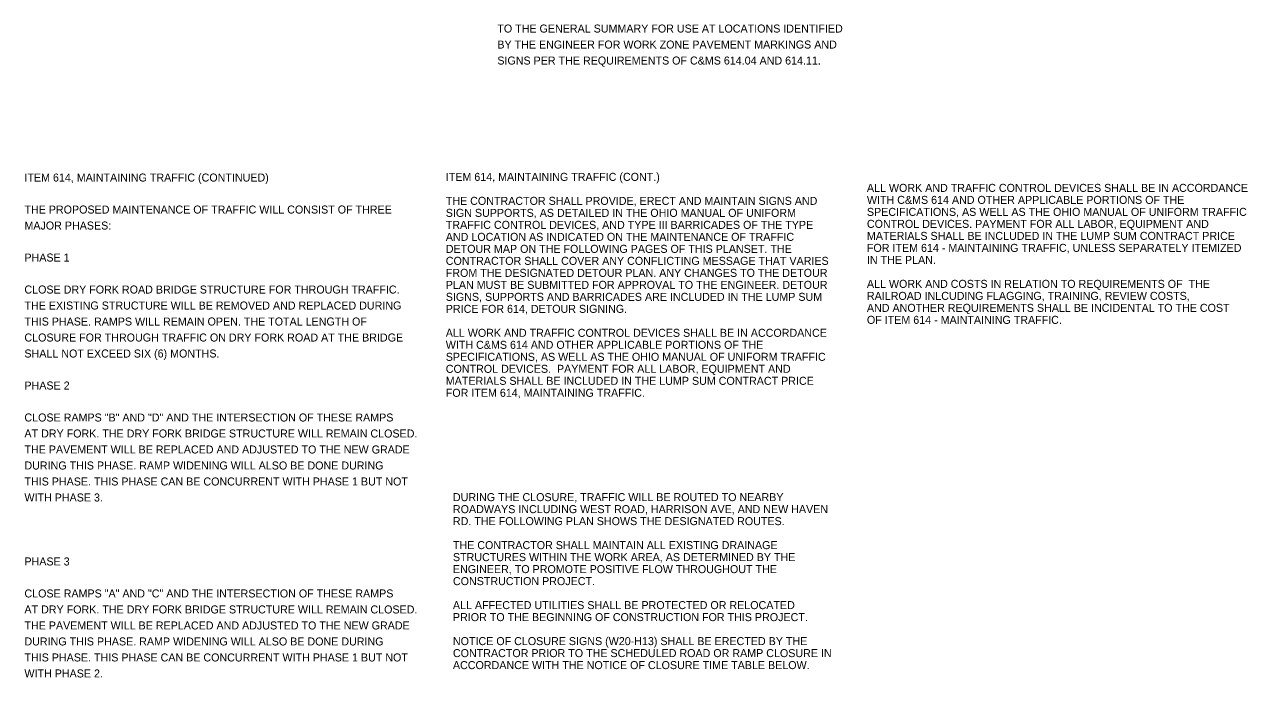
# Model space of a CAD drawing. Extents: x -65.5 to 34, y -24.3 to 23.1.
# Drawn here: x -65.5 to -44.1, y -0.83 to 10.6 of the extents above; entities that cross this region are included whole.
import ezdxf

# ---------------------------------------------------------------- set-up
doc = ezdxf.new("R2010")
doc.units = 0
doc.layers.add('SH_Text', color=7, linetype='Continuous')

msp = doc.modelspace()

# ---------------------------------------------------------------- texts
at = {"layer": 'SH_Text'}
for s, p in [('TO THE GENERAL SUMMARY FOR USE AT LOCATIONS IDENTIFIED', (-57.226, 10.462)), ('BY THE ENGINEER FOR WORK ZONE PAVEMENT MARKINGS AND', (-57.226, 10.182)), ('SIGNS PER THE REQUIREMENTS OF C&MS 614.04 AND 614.11.', (-57.226, 9.902)), ('ITEM 614, MAINTAINING TRAFFIC (CONTINUED)', (-65.5, 7.854)), ('ITEM 614, MAINTAINING TRAFFIC (CONT.)', (-58.128, 7.866)), ('ALL WORK AND TRAFFIC CONTROL DEVICES SHALL BE IN ACCORDANCE ', (-50.76, 7.673)), ('THE CONTRACTOR SHALL PROVIDE, ERECT AND MAINTAIN SIGNS AND ', (-58.128, 7.446)), ('WITH C&MS 614 AND OTHER APPLICABLE PORTIONS OF THE ', (-50.76, 7.463)), ('THE PROPOSED MAINTENANCE OF TRAFFIC WILL CONSIST OF THREE', (-65.5, 7.294)), ('SIGN SUPPORTS, AS DETAILED IN THE OHIO MANUAL OF UNIFORM ', (-58.128, 7.236)), ('SPECIFICATIONS, AS WELL AS THE OHIO MANUAL OF UNIFORM TRAFFIC ', (-50.76, 7.253)), ('MAJOR PHASES:', (-65.5, 7.014)), ('TRAFFIC CONTROL DEVICES, AND TYPE III BARRICADES OF THE TYPE ', (-58.128, 7.026)), ('CONTROL DEVICES. PAYMENT FOR ALL LABOR, EQUIPMENT AND ', (-50.76, 7.043)), ('AND LOCATION AS INDICATED ON THE MAINTENANCE OF TRAFFIC ', (-58.128, 6.816)), ('MATERIALS SHALL BE INCLUDED IN THE LUMP SUM CONTRACT PRICE ', (-50.76, 6.833)), ('DETOUR MAP ON THE FOLLOWING PAGES OF THIS PLANSET. THE ', (-58.128, 6.606)), ('FOR ITEM 614 - MAINTAINING TRAFFIC, UNLESS SEPARATELY ITEMIZED ', (-50.76, 6.623)), ('PHASE 1', (-65.5, 6.454)), ('CONTRACTOR SHALL COVER ANY CONFLICTING MESSAGE THAT VARIES ', (-58.128, 6.396)), ('IN THE PLAN.', (-50.76, 6.413)), ('FROM THE DESIGNATED DETOUR PLAN. ANY CHANGES TO THE DETOUR ', (-58.128, 6.186)), ('CLOSE DRY FORK ROAD BRIDGE STRUCTURE FOR THROUGH TRAFFIC. ', (-65.5, 5.894)), ('PLAN MUST BE SUBMITTED FOR APPROVAL TO THE ENGINEER. DETOUR ', (-58.128, 5.976)), ('ALL WORK AND COSTS IN RELATION TO REQUIREMENTS OF  THE ', (-50.76, 5.993)), ('SIGNS, SUPPORTS AND BARRICADES ARE INCLUDED IN THE LUMP SUM ', (-58.128, 5.766)), ('RAILROAD INLCUDING FLAGGING, TRAINING, REVIEW COSTS,', (-50.76, 5.783)), ('THE EXISTING STRUCTURE WILL BE REMOVED AND REPLACED DURING ', (-65.5, 5.614)), ('PRICE FOR 614, DETOUR SIGNING.', (-58.128, 5.556)), ('AND ANOTHER REQUIREMENTS SHALL BE INCIDENTAL TO THE COST', (-50.76, 5.573)), ('THIS PHASE. RAMPS WILL REMAIN OPEN. THE TOTAL LENGTH OF ', (-65.5, 5.334)), ('OF ITEM 614 - MAINTAINING TRAFFIC.', (-50.76, 5.363)), ('CLOSURE FOR THROUGH TRAFFIC ON DRY FORK ROAD AT THE BRIDGE ', (-65.5, 5.054)), ('ALL WORK AND TRAFFIC CONTROL DEVICES SHALL BE IN ACCORDANCE ', (-58.128, 5.136)), ('WITH C&MS 614 AND OTHER APPLICABLE PORTIONS OF THE ', (-58.128, 4.926)), ('SHALL NOT EXCEED SIX (6) MONTHS. ', (-65.5, 4.774)), ('SPECIFICATIONS, AS WELL AS THE OHIO MANUAL OF UNIFORM TRAFFIC ', (-58.128, 4.716)), ('CONTROL DEVICES.  PAYMENT FOR ALL LABOR, EQUIPMENT AND ', (-58.128, 4.506)), ('PHASE 2', (-65.5, 4.214)), ('MATERIALS SHALL BE INCLUDED IN THE LUMP SUM CONTRACT PRICE ', (-58.128, 4.296)), ('FOR ITEM 614, MAINTAINING TRAFFIC.', (-58.128, 4.086)), ('CLOSE RAMPS "B" AND "D" AND THE INTERSECTION OF THESE RAMPS ', (-65.5, 3.654)), ('AT DRY FORK. THE DRY FORK BRIDGE STRUCTURE WILL REMAIN CLOSED. ', (-65.5, 3.374)), ('THE PAVEMENT WILL BE REPLACED AND ADJUSTED TO THE NEW GRADE ', (-65.5, 3.094)), ('DURING THIS PHASE. RAMP WIDENING WILL ALSO BE DONE DURING ', (-65.5, 2.814)), ('THIS PHASE. THIS PHASE CAN BE CONCURRENT WITH PHASE 1 BUT NOT ', (-65.5, 2.534)), ('WITH PHASE 3.', (-65.5, 2.254)), ('DURING THE CLOSURE, TRAFFIC WILL BE ROUTED TO NEARBY ', (-58.003, 2.26)), ('ROADWAYS INCLUDING WEST ROAD, HARRISON AVE, AND NEW HAVEN ', (-58.003, 2.05)), ('RD. THE FOLLOWING PLAN SHOWS THE DESIGNATED ROUTES. ', (-58.003, 1.84)), ('THE CONTRACTOR SHALL MAINTAIN ALL EXISTING DRAINAGE ', (-58.003, 1.42)), ('STRUCTURES WITHIN THE WORK AREA, AS DETERMINED BY THE ', (-58.003, 1.21)), ('PHASE 3', (-65.5, 1.134)), ('ENGINEER, TO PROMOTE POSITIVE FLOW THROUGHOUT THE ', (-58.003, 1)), ('CONSTRUCTION PROJECT.', (-58.003, 0.79)), ('CLOSE RAMPS "A" AND "C" AND THE INTERSECTION OF THESE RAMPS ', (-65.5, 0.574)), ('AT DRY FORK. THE DRY FORK BRIDGE STRUCTURE WILL REMAIN CLOSED. ', (-65.5, 0.294)), ('ALL AFFECTED UTILITIES SHALL BE PROTECTED OR RELOCATED ', (-58.003, 0.37)), ('PRIOR TO THE BEGINNING OF CONSTRUCTION FOR THIS PROJECT.', (-58.003, 0.16)), ('THE PAVEMENT WILL BE REPLACED AND ADJUSTED TO THE NEW GRADE ', (-65.5, 0.014)), ('DURING THIS PHASE. RAMP WIDENING WILL ALSO BE DONE DURING ', (-65.5, -0.266)), ('NOTICE OF CLOSURE SIGNS (W20-H13) SHALL BE ERECTED BY THE ', (-58.003, -0.26)), ('THIS PHASE. THIS PHASE CAN BE CONCURRENT WITH PHASE 1 BUT NOT ', (-65.5, -0.546)), ('CONTRACTOR PRIOR TO THE SCHEDULED ROAD OR RAMP CLOSURE IN ', (-58.003, -0.47)), ('ACCORDANCE WITH THE NOTICE OF CLOSURE TIME TABLE BELOW.', (-58.003, -0.68)), ('WITH PHASE 2.', (-65.5, -0.826))]:
    msp.add_text(s, height=0.14, dxfattribs=at).set_placement(p)

doc.saveas('drawing.dxf')
